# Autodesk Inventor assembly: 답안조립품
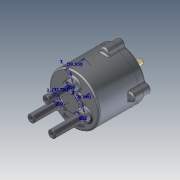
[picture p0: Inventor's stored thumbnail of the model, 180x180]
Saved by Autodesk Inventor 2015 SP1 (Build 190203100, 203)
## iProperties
Created: 2015-05
Part Number: 답안조립품
Document SubType Name: Assembly
Designer: jckim
Mass: 2156.77 g
Surface Area: 1801.22 cm^2
Volume: 438.523 cm^3
Density: 4.91826 g/cm^3
Author: jckim
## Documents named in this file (14)
- C:\Users\jckim\Documents\Inventor1급\답안조립품.iam
- C:\Users\jckim\Documents\Inventor1급\2014-02-20 1급 공용부품\몸체.ipt
- C:\Users\jckim\Documents\Inventor1급\2014-02-20 1급 공용부품\슬라이드 축.ipt
- C:\Users\jckim\Documents\Inventor1급\2014-02-20 1급 공용부품\베어링 NA 4900.ipt
- C:\Users\jckim\Documents\Inventor1급\2014-02-20 1급 공용부품\메인 축.ipt
- C:\Users\jckim\Documents\Inventor1급\2014-02-20 1급 공용부품\멈춤링 10 x 1.ipt
- C:\Users\jckim\Documents\Inventor1급\2014-02-20 1급 공용부품\멈춤링 22 x 1.2.ipt
- C:\Users\jckim\Documents\Inventor1급\2014-02-20 1급 공용부품\판캠.ipt
- C:\Users\jckim\Documents\Inventor1급\2014-02-20 1급 공용부품\커버.ipt
- C:\Users\jckim\Documents\Inventor1급\2014-02-20 1급 공용부품\오일실.ipt
- C:\Users\jckim\Documents\Inventor1급\가변 스프링_01.ipt
- C:\Users\jckim\Documents\Inventor1급\가변 스프링_02.ipt
- C:\Users\jckim\Documents\Inventor1급\가변 스프링_03.ipt
- C:\Users\jckim\Documents\Inventor1급\2014-02-20 1급 공용부품\M5x0.5x20.ipt
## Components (7 placed, 4 different names)
1. 가변 스프링_01:1
2. 가변 스프링_02:1
3. 가변 스프링_03:1
4. M5x0.5x20:1
5. M5x0.5x20:2
6. M5x0.5x20:3
7. M5x0.5x20:4
